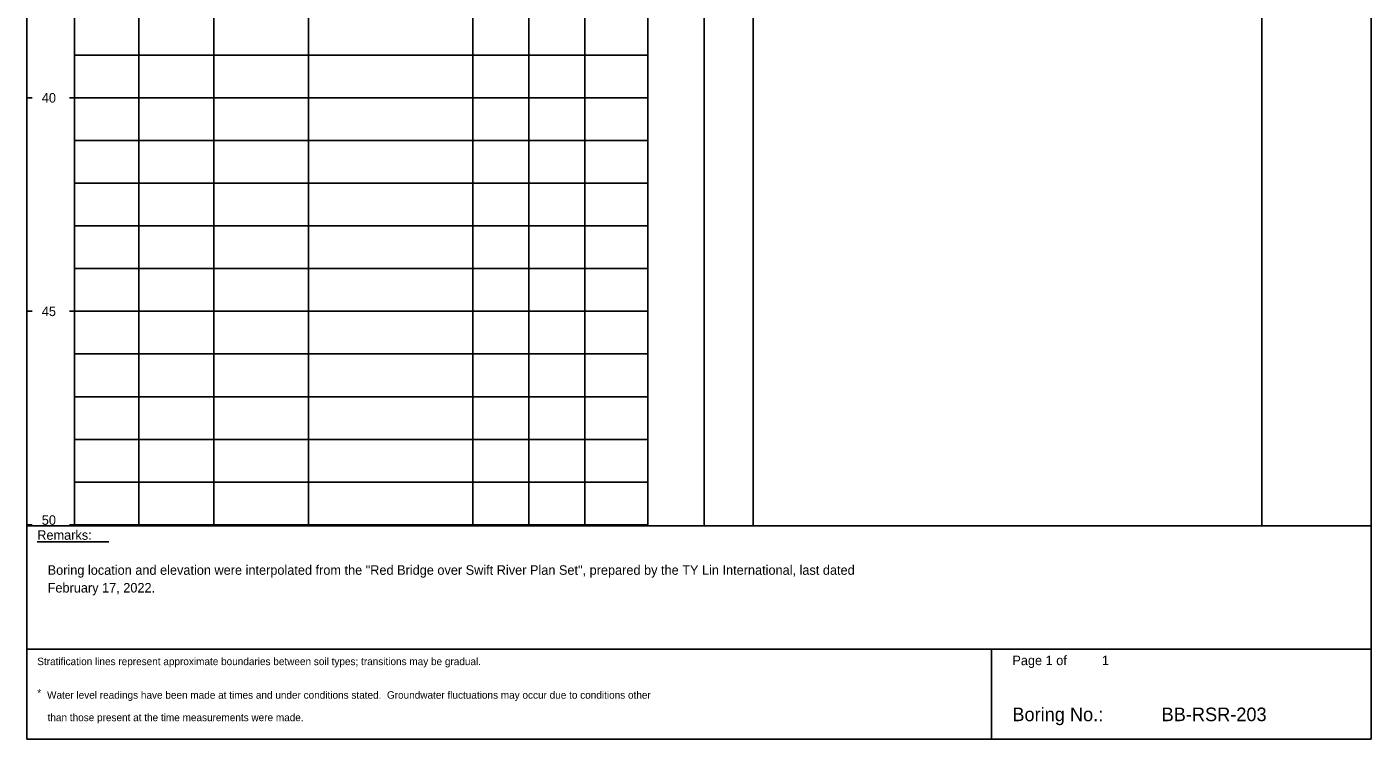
# Model space of a CAD drawing. Extents: x 9419 to 9552, y 6780 to 6865.
# Drawn here: x 9460.28 to 9491.78, y 6791.99 to 6808.67 of the extents above; entities that cross this region are included whole.
import ezdxf

# ---------------------------------------------------------------- set-up
doc = ezdxf.new("R2010")
doc.units = 0
doc.layers.add('7', color=7, linetype='Continuous')

msp = doc.modelspace()

# ---------------------------------------------------------------- linework, layer by layer
at = {"layer": '7'}
msp.add_line((9460.526, 6796.614), (9462.203, 6796.614), dxfattribs=at)
for points in [[(9460.282, 6822.038), (9460.282, 6791.992)], [(9461.4, 6822.038), (9461.4, 6796.983)], [(9462.909, 6822.038), (9462.909, 6796.983)], [(9464.665, 6822.038), (9464.665, 6796.983)], [(9466.879, 6822.038), (9466.879, 6796.983)], [(9470.734, 6822.038), (9470.734, 6796.983)], [(9472.046, 6822.038), (9472.046, 6796.983)], [(9473.359, 6822.038), (9473.359, 6796.983)], [(9474.835, 6822.038), (9474.835, 6796.983)], [(9476.148, 6822.038), (9476.148, 6796.983)], [(9477.296, 6822.038), (9477.296, 6796.983)], [(9489.214, 6822.038), (9489.214, 6796.983)], [(9491.778, 6822.038), (9491.778, 6791.992)], [(9461.4, 6808.011), (9462.909, 6808.011)], [(9462.909, 6808.011), (9464.665, 6808.011)], [(9464.665, 6808.011), (9466.879, 6808.011)], [(9466.879, 6808.011), (9470.734, 6808.011)], [(9470.734, 6808.011), (9472.046, 6808.011)], [(9472.046, 6808.011), (9473.359, 6808.011)], [(9473.359, 6808.011), (9474.835, 6808.011)], [(9460.282, 6807.011), (9460.404, 6807.011)], [(9461.4, 6807.011), (9461.279, 6807.011)], [(9461.4, 6807.011), (9462.909, 6807.011)], [(9462.909, 6807.011), (9464.665, 6807.011)], [(9464.665, 6807.011), (9466.879, 6807.011)], [(9466.879, 6807.011), (9470.734, 6807.011)], [(9470.734, 6807.011), (9472.046, 6807.011)], [(9472.046, 6807.011), (9473.359, 6807.011)], [(9473.359, 6807.011), (9474.835, 6807.011)], [(9461.4, 6806.011), (9462.909, 6806.011)], [(9462.909, 6806.011), (9464.665, 6806.011)], [(9464.665, 6806.011), (9466.879, 6806.011)], [(9466.879, 6806.011), (9470.734, 6806.011)], [(9470.734, 6806.011), (9472.046, 6806.011)], [(9472.046, 6806.011), (9473.359, 6806.011)], [(9473.359, 6806.011), (9474.835, 6806.011)], [(9461.4, 6805.011), (9462.909, 6805.011)], [(9462.909, 6805.011), (9464.665, 6805.011)], [(9464.665, 6805.011), (9466.879, 6805.011)], [(9466.879, 6805.011), (9470.734, 6805.011)], [(9470.734, 6805.011), (9472.046, 6805.011)], [(9472.046, 6805.011), (9473.359, 6805.011)], [(9473.359, 6805.011), (9474.835, 6805.011)], [(9461.4, 6804.011), (9462.909, 6804.011)], [(9462.909, 6804.011), (9464.665, 6804.011)], [(9464.665, 6804.011), (9466.879, 6804.011)], [(9466.879, 6804.011), (9470.734, 6804.011)], [(9470.734, 6804.011), (9472.046, 6804.011)], [(9472.046, 6804.011), (9473.359, 6804.011)], [(9473.359, 6804.011), (9474.835, 6804.011)], [(9461.4, 6803.011), (9462.909, 6803.011)], [(9462.909, 6803.011), (9464.665, 6803.011)], [(9464.665, 6803.011), (9466.879, 6803.011)], [(9466.879, 6803.011), (9470.734, 6803.011)], [(9470.734, 6803.011), (9472.046, 6803.011)], [(9472.046, 6803.011), (9473.359, 6803.011)], [(9473.359, 6803.011), (9474.835, 6803.011)], [(9460.282, 6802.011), (9460.404, 6802.011)], [(9461.4, 6802.011), (9461.279, 6802.011)], [(9461.4, 6802.011), (9462.909, 6802.011)], [(9462.909, 6802.011), (9464.665, 6802.011)], [(9464.665, 6802.011), (9466.879, 6802.011)], [(9466.879, 6802.011), (9470.734, 6802.011)], [(9470.734, 6802.011), (9472.046, 6802.011)], [(9472.046, 6802.011), (9473.359, 6802.011)], [(9473.359, 6802.011), (9474.835, 6802.011)], [(9461.4, 6801.011), (9462.909, 6801.011)], [(9462.909, 6801.011), (9464.665, 6801.011)], [(9464.665, 6801.011), (9466.879, 6801.011)], [(9466.879, 6801.011), (9470.734, 6801.011)], [(9470.734, 6801.011), (9472.046, 6801.011)], [(9472.046, 6801.011), (9473.359, 6801.011)], [(9473.359, 6801.011), (9474.835, 6801.011)], [(9461.4, 6800.011), (9462.909, 6800.011)], [(9462.909, 6800.011), (9464.665, 6800.011)], [(9464.665, 6800.011), (9466.879, 6800.011)], [(9466.879, 6800.011), (9470.734, 6800.011)], [(9470.734, 6800.011), (9472.046, 6800.011)], [(9472.046, 6800.011), (9473.359, 6800.011)], [(9473.359, 6800.011), (9474.835, 6800.011)], [(9461.4, 6799.011), (9462.909, 6799.011)], [(9462.909, 6799.011), (9464.665, 6799.011)], [(9464.665, 6799.011), (9466.879, 6799.011)], [(9466.879, 6799.011), (9470.734, 6799.011)], [(9470.734, 6799.011), (9472.046, 6799.011)], [(9472.046, 6799.011), (9473.359, 6799.011)], [(9473.359, 6799.011), (9474.835, 6799.011)], [(9461.4, 6798.011), (9462.909, 6798.011)], [(9462.909, 6798.011), (9464.665, 6798.011)], [(9464.665, 6798.011), (9466.879, 6798.011)], [(9466.879, 6798.011), (9470.734, 6798.011)], [(9470.734, 6798.011), (9472.046, 6798.011)], [(9472.046, 6798.011), (9473.359, 6798.011)], [(9473.359, 6798.011), (9474.835, 6798.011)], [(9460.282, 6797.011), (9460.404, 6797.011)], [(9460.282, 6796.983), (9491.778, 6796.983)], [(9461.4, 6797.011), (9461.279, 6797.011)], [(9461.4, 6797.011), (9462.909, 6797.011)], [(9462.909, 6797.011), (9464.665, 6797.011)], [(9464.665, 6797.011), (9466.879, 6797.011)], [(9466.879, 6797.011), (9470.734, 6797.011)], [(9470.734, 6797.011), (9472.046, 6797.011)], [(9472.046, 6797.011), (9473.359, 6797.011)], [(9473.359, 6797.011), (9474.835, 6797.011)], [(9460.282, 6794.1), (9491.778, 6794.1)], [(9482.887, 6794.1), (9482.887, 6791.992)], [(9460.282, 6791.992), (9491.778, 6791.992)]]:
    msp.add_lwpolyline(points, dxfattribs=at)

# ---------------------------------------------------------------- texts
for s, height, p in [('40', 0.2228, (9460.632, 6806.899)), ('45', 0.2228, (9460.632, 6801.899)), ('50', 0.2228, (9460.632, 6797.011)), ('Remarks:', 0.2228, (9460.526, 6796.66)), ('Boring location and elevation were interpolated from the "Red Bridge over Swift River Plan Set", prepared by the TY Lin International, last dated', 0.222801, (9460.769, 6795.84)), ('February 17, 2022.', 0.2228, (9460.769, 6795.425)), ('Stratification lines represent approximate boundaries between soil types; transitions may be gradual.', 0.175058, (9460.526, 6793.724)), ('Page 1 of ', 0.2228, (9483.373, 6793.724)), ('1', 0.223, (9485.47, 6793.724)), ('*', 0.175, (9460.525, 6792.987)), (' Water level readings have been made at times and under conditions stated.  Groundwater fluctuations may occur due to conditions other', 0.175058, (9460.69, 6792.938)), ('Boring No.:', 0.31829, (9483.373, 6792.412)), ('than those present at the time measurements were made.', 0.17506, (9460.768, 6792.412)), ('BB-RSR-203', 0.3183, (9486.87, 6792.412))]:
    msp.add_text(s, height=height, dxfattribs=at).set_placement(p)

doc.saveas('drawing.dxf')
